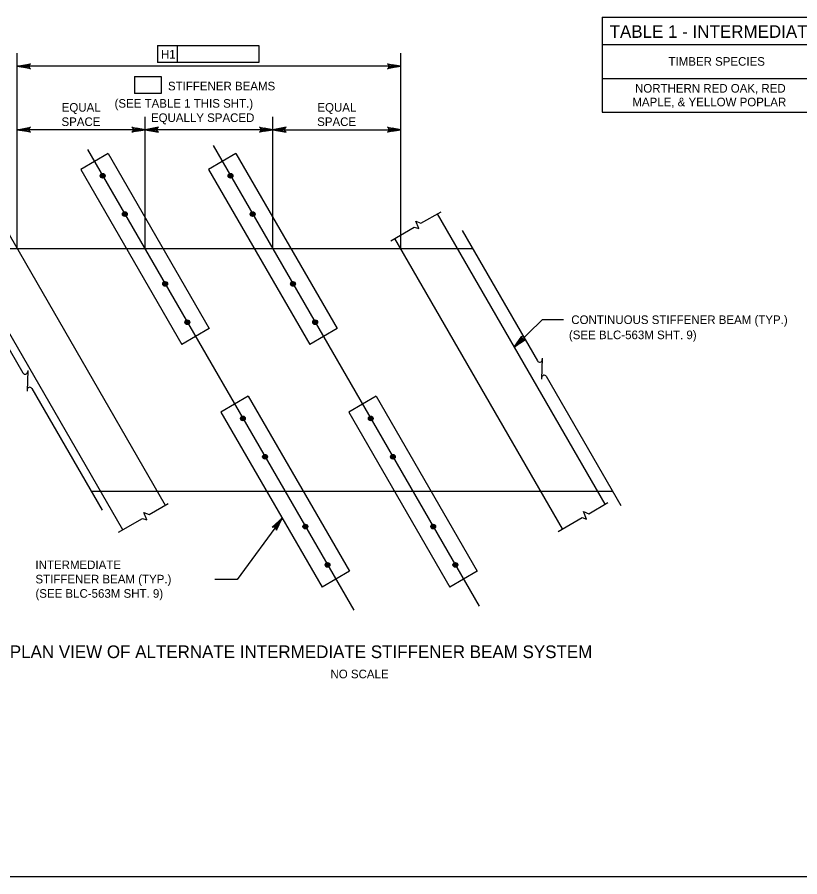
# Model space of a CAD drawing. Extents: x 638268 to 640277, y 295465 to 298435.
# Drawn here: x 639628.9 to 639902.1, y 296668.5 to 296968.5 of the extents above; entities that cross this region are included whole.
import ezdxf

# ---------------------------------------------------------------- set-up
doc = ezdxf.new("R2010")
doc.units = 0
for name, color, linetype in [('2', 7, 'Continuous'), ('3', 7, 'Continuous'), ('4', 7, 'Continuous'), ('8', 7, 'Continuous')]:
    doc.layers.add(name, color=color, linetype=linetype)

msp = doc.modelspace()

# ---------------------------------------------------------------- linework, layer by layer
at = {"layer": '2'}
for p, q in [((639787.93, 296887.61), (639605.87, 296887.61)), ((639836.89, 296802.91), (639654.83, 296802.91)), ((640102.46, 296668.46), (639316.46, 296668.46))]:
    msp.add_line(p, q, dxfattribs=at)
at = {"layer": '3'}
for p, q in [((639660.62, 296920.9), (639651.08, 296915.38)), ((639660.62, 296920.9), (639695.94, 296859.8)), ((639705.26, 296920.9), (639695.71, 296915.38)), ((639705.26, 296920.9), (639740.57, 296859.8)), ((639651.08, 296915.38), (639686.4, 296854.29)), ((639695.71, 296915.38), (639731.03, 296854.29)), ((639769.85, 296896.57), (639776.87, 296900.62)), ((639622.02, 296899.51), (639680.61, 296798.15)), ((639769.07, 296894.71), (639768.05, 296897.31)), ((639768.05, 296897.31), (639769.85, 296896.57)), ((639775.51, 296899.84), (639834.1, 296798.48)), ((639759.35, 296890.5), (639767.51, 296895.22)), ((639767.51, 296895.22), (639769.07, 296894.71)), ((639784.22, 296894.04), (639810.51, 296848.55)), ((639603.62, 296891.5), (639630.89, 296844.33)), ((639819.28, 296789.91), (639760.69, 296891.27)), ((639665.78, 296789.58), (639607.2, 296890.94)), ((639812.2, 296862.83), (639802.41, 296853.32)), ((639695.94, 296859.8), (639686.4, 296854.29)), ((639740.57, 296859.8), (639731.03, 296854.29)), ((639812.22, 296849.46), (639811.95, 296842.19)), ((639632.6, 296845.24), (639632.33, 296837.97)), ((639813.62, 296843.17), (639839.68, 296798.08)), ((639634, 296838.95), (639658.59, 296796.39)), ((639709.58, 296836.2), (639700.04, 296830.68)), ((639709.58, 296836.2), (639744.9, 296775.1)), ((639754.22, 296836.2), (639744.67, 296830.68)), ((639754.22, 296836.2), (639789.54, 296775.1)), ((639700.04, 296830.68), (639735.36, 296769.58)), ((639744.67, 296830.68), (639779.99, 296769.58)), ((639674.95, 296794.88), (639681.64, 296798.75)), ((639828.44, 296795.21), (639835.13, 296799.08)), ((639674.16, 296793.02), (639673.15, 296795.62)), ((639673.15, 296795.62), (639674.95, 296794.88)), ((639827.66, 296793.35), (639826.64, 296795.95)), ((639826.64, 296795.95), (639828.44, 296795.21)), ((639664.29, 296788.72), (639672.61, 296793.53)), ((639672.61, 296793.53), (639674.16, 296793.02)), ((639817.78, 296789.05), (639826.1, 296793.86)), ((639826.1, 296793.86), (639827.66, 296793.35)), ((639744.9, 296775.1), (639735.36, 296769.58)), ((639789.54, 296775.1), (639779.99, 296769.58))]:
    msp.add_line(p, q, dxfattribs=at)
msp.add_lwpolyline([(639802.4, 296853.32), (639805.14, 296857.19), (639805.06, 296856.77), (639805.14, 296856.41), (639805.32, 296856.15), (639805.58, 296855.96), (639805.93, 296855.87), (639806.36, 296855.94), (639802.4, 296853.32), (639805.93, 296855.87), (639805.58, 296855.96), (639802.4, 296853.32), (639805.32, 296856.15), (639805.14, 296856.41), (639802.4, 296853.32), (639805.06, 296856.77)], dxfattribs=at)
for centre, radius in [((639658.73, 296913.16), 0.833), ((639658.73, 296913.16), 0.738), ((639658.73, 296913.16), 0.625), ((639658.73, 296913.16), 0.417), ((639658.73, 296913.16), 0.208), ((639703.37, 296913.16), 0.833), ((639703.37, 296913.16), 0.738), ((639703.37, 296913.16), 0.625), ((639703.37, 296913.16), 0.417), ((639703.37, 296913.16), 0.208), ((639666.47, 296899.78), 0.833), ((639666.47, 296899.78), 0.738), ((639666.47, 296899.78), 0.625), ((639666.47, 296899.78), 0.417), ((639711.1, 296899.78), 0.833), ((639711.1, 296899.78), 0.738), ((639711.1, 296899.78), 0.625), ((639711.1, 296899.78), 0.417), ((639666.47, 296899.78), 0.208), ((639711.1, 296899.78), 0.208), ((639680.55, 296875.41), 0.833), ((639680.55, 296875.41), 0.738), ((639680.55, 296875.41), 0.625), ((639725.19, 296875.41), 0.833), ((639725.19, 296875.41), 0.738), ((639725.19, 296875.41), 0.625), ((639680.55, 296875.41), 0.417), ((639680.55, 296875.41), 0.208), ((639725.19, 296875.41), 0.417), ((639725.19, 296875.41), 0.208), ((639688.29, 296862.03), 0.833), ((639688.29, 296862.03), 0.738), ((639688.29, 296862.03), 0.625), ((639688.29, 296862.03), 0.417), ((639688.29, 296862.03), 0.208), ((639732.92, 296862.03), 0.833), ((639732.92, 296862.03), 0.738), ((639732.92, 296862.03), 0.625), ((639732.92, 296862.03), 0.417), ((639732.92, 296862.03), 0.208), ((639707.69, 296828.46), 0.833), ((639707.69, 296828.46), 0.738), ((639707.69, 296828.46), 0.625), ((639707.69, 296828.46), 0.417), ((639707.69, 296828.46), 0.208), ((639752.33, 296828.46), 0.833), ((639752.33, 296828.46), 0.738), ((639752.33, 296828.46), 0.625), ((639752.33, 296828.46), 0.417), ((639752.33, 296828.46), 0.208), ((639715.43, 296815.08), 0.833), ((639715.43, 296815.08), 0.738), ((639715.43, 296815.08), 0.625), ((639715.43, 296815.08), 0.417), ((639715.43, 296815.08), 0.208), ((639760.06, 296815.08), 0.833), ((639760.06, 296815.08), 0.738), ((639760.06, 296815.08), 0.625), ((639760.06, 296815.08), 0.417), ((639760.06, 296815.08), 0.208), ((639729.51, 296790.71), 0.833), ((639729.51, 296790.71), 0.738), ((639729.51, 296790.71), 0.625), ((639729.51, 296790.71), 0.417), ((639729.51, 296790.71), 0.208), ((639774.15, 296790.71), 0.833), ((639774.15, 296790.71), 0.738), ((639774.15, 296790.71), 0.625), ((639774.15, 296790.71), 0.417), ((639774.15, 296790.71), 0.208), ((639737.25, 296777.33), 0.833), ((639737.25, 296777.33), 0.738), ((639737.25, 296777.33), 0.625), ((639737.25, 296777.33), 0.417), ((639737.25, 296777.33), 0.208), ((639781.88, 296777.33), 0.833), ((639781.88, 296777.33), 0.738), ((639781.88, 296777.33), 0.625), ((639781.88, 296777.33), 0.417), ((639781.88, 296777.33), 0.208)]:
    msp.add_circle(centre, radius, dxfattribs=at)
for centre, start, end in [((639811.3, 296849.01), 210.0292, 0.0292), ((639631.67, 296844.79), 210.0292, 0.0292), ((639812.88, 296842.64), 35.3578, 177.8964), ((639633.26, 296838.42), 35.3578, 177.8964)]:
    msp.add_arc(centre, 0.909, start, end, dxfattribs=at)
at = {"layer": '4'}
for p, q in [((639677.91, 296958.64), (639677.91, 296952.73)), ((639677.91, 296958.64), (639713.21, 296958.64)), ((639684.8, 296958.64), (639684.8, 296952.73)), ((639713.21, 296958.64), (639713.21, 296952.73)), ((639628.9, 296887.61), (639628.9, 296955.91)), ((639762.81, 296887.61), (639762.81, 296955.91)), ((639762.81, 296951.41), (639628.9, 296951.41)), ((639713.21, 296952.73), (639677.91, 296952.73)), ((639669.83, 296947.8), (639679.11, 296947.8)), ((639669.83, 296947.8), (639669.83, 296941.9)), ((639679.11, 296947.8), (639679.11, 296941.9)), ((639679.11, 296941.9), (639669.83, 296941.9)), ((639628.9, 296887.61), (639628.9, 296933.76)), ((639673.54, 296887.61), (639673.54, 296933.76)), ((639718.17, 296887.61), (639718.17, 296933.76)), ((639762.81, 296887.61), (639762.81, 296933.76)), ((639670.54, 296929.26), (639628.9, 296929.26)), ((639715.17, 296929.26), (639676.54, 296929.26)), ((639721.17, 296929.26), (639762.81, 296929.26)), ((639653.49, 296922.3), (639746.39, 296761.57)), ((639697.31, 296923.7), (639790.21, 296762.97)), ((639819.68, 296862.83), (639812.2, 296862.83)), ((639705.75, 296772.23), (639697.91, 296772.23))]:
    msp.add_line(p, q, dxfattribs=at)
for points in [[(639628.9, 296951.41), (639633.56, 296952.28), (639633.2, 296952.03), (639633.02, 296951.72), (639632.96, 296951.41), (639633.02, 296951.1), (639633.2, 296950.78), (639633.56, 296950.54), (639628.9, 296951.41), (639633.2, 296950.78), (639633.02, 296951.1), (639628.9, 296951.41), (639632.96, 296951.41), (639633.02, 296951.72), (639628.9, 296951.41), (639633.2, 296952.03)], [(639762.81, 296951.41), (639758.15, 296950.54), (639758.5, 296950.78), (639758.69, 296951.1), (639758.74, 296951.41), (639758.69, 296951.72), (639758.5, 296952.03), (639758.15, 296952.28), (639762.81, 296951.41), (639758.5, 296952.03), (639758.69, 296951.72), (639762.81, 296951.41), (639758.74, 296951.41), (639758.69, 296951.1), (639762.81, 296951.41), (639758.5, 296950.78)], [(639628.9, 296929.26), (639633.56, 296930.13), (639633.2, 296929.89), (639633.02, 296929.57), (639632.96, 296929.26), (639633.02, 296928.95), (639633.2, 296928.64), (639633.56, 296928.39), (639628.9, 296929.26), (639633.2, 296928.64), (639633.02, 296928.95), (639628.9, 296929.26), (639632.96, 296929.26), (639633.02, 296929.57), (639628.9, 296929.26), (639633.2, 296929.89)], [(639673.54, 296929.26), (639668.87, 296928.39), (639669.23, 296928.64), (639669.42, 296928.95), (639669.47, 296929.26), (639669.42, 296929.57), (639669.23, 296929.89), (639668.87, 296930.13), (639673.54, 296929.26), (639669.23, 296929.89), (639669.42, 296929.57), (639673.54, 296929.26), (639669.47, 296929.26), (639669.42, 296928.95), (639673.54, 296929.26), (639669.23, 296928.64)], [(639673.54, 296929.26), (639678.2, 296928.39), (639677.84, 296928.64), (639677.65, 296928.95), (639677.6, 296929.26), (639677.65, 296929.57), (639677.84, 296929.89), (639678.2, 296930.13), (639673.54, 296929.26), (639677.84, 296929.89), (639677.65, 296929.57), (639673.54, 296929.26), (639677.6, 296929.26), (639677.65, 296928.95), (639673.54, 296929.26), (639677.84, 296928.64)], [(639718.17, 296929.26), (639713.51, 296928.39), (639713.87, 296928.64), (639714.05, 296928.95), (639714.11, 296929.26), (639714.05, 296929.57), (639713.87, 296929.89), (639713.51, 296930.13), (639718.17, 296929.26), (639713.87, 296929.89), (639714.05, 296929.57), (639718.17, 296929.26), (639714.11, 296929.26), (639714.05, 296928.95), (639718.17, 296929.26), (639713.87, 296928.64)], [(639718.17, 296929.26), (639722.83, 296928.39), (639722.47, 296928.64), (639722.29, 296928.95), (639722.23, 296929.26), (639722.29, 296929.57), (639722.47, 296929.89), (639722.83, 296930.13), (639718.17, 296929.26), (639722.47, 296929.89), (639722.29, 296929.57), (639718.17, 296929.26), (639722.23, 296929.26), (639722.29, 296928.95), (639718.17, 296929.26), (639722.47, 296928.64)], [(639762.81, 296929.26), (639758.15, 296928.39), (639758.5, 296928.64), (639758.69, 296928.95), (639758.74, 296929.26), (639758.69, 296929.57), (639758.5, 296929.89), (639758.15, 296930.13), (639762.81, 296929.26), (639758.5, 296929.89), (639758.69, 296929.57), (639762.81, 296929.26), (639758.74, 296929.26), (639758.69, 296928.95), (639762.81, 296929.26), (639758.5, 296928.64)], [(639721.42, 296793.69), (639705.65, 296772.19)], [(639721.42, 296793.69), (639717.96, 296790.45), (639718.37, 296790.59), (639718.74, 296790.56), (639719.02, 296790.41), (639719.24, 296790.18), (639719.38, 296789.85), (639719.37, 296789.41), (639721.42, 296793.69), (639719.38, 296789.85), (639719.24, 296790.18), (639721.42, 296793.69), (639719.02, 296790.41), (639718.74, 296790.56), (639721.42, 296793.69), (639718.37, 296790.59)]]:
    msp.add_lwpolyline(points, dxfattribs=at)
for points in [[(639631.9, 296951.91), (639631.9, 296950.91), (639628.9, 296951.41)], [(639759.81, 296951.91), (639759.81, 296950.91), (639762.81, 296951.41)], [(639631.9, 296929.76), (639631.9, 296928.76), (639628.9, 296929.26)], [(639670.54, 296929.76), (639670.54, 296928.76), (639673.54, 296929.26)], [(639676.54, 296929.76), (639676.54, 296928.76), (639673.54, 296929.26)], [(639715.17, 296929.76), (639715.17, 296928.76), (639718.17, 296929.26)], [(639721.17, 296929.76), (639721.17, 296928.76), (639718.17, 296929.26)], [(639759.81, 296929.76), (639759.81, 296928.76), (639762.81, 296929.26)], [(639721.42, 296793.69), (639719.85, 296791.12), (639719.45, 296791.42)]]:
    msp.add_lwpolyline(points, close=True, dxfattribs=at)
at = {"layer": '8'}
for p, q in [((639833.15, 296968.52), (640055.35, 296968.52)), ((639833.15, 296968.52), (639833.15, 296935.36)), ((639833.15, 296958.99), (640055.35, 296958.99)), ((639833.15, 296947.17), (640055.35, 296947.17)), ((639833.15, 296935.36), (640055.35, 296935.36))]:
    msp.add_line(p, q, dxfattribs=at)

# ---------------------------------------------------------------- texts
at = {"layer": '4'}
for s, height, p in [('TABLE 1 - INTERMEDIATE STIFFENER BEAM DESIGN DATA', 4.4292, (639835.73, 296961.31)), ('H1', 3, (639679.09, 296954.1)), ('TIMBER SPECIES', 3, (639856.29, 296951.58)), ('STIFFENER BEAMS', 3, (639681.53, 296942.98)), ('NORTHERN RED OAK, RED', 3, (639844.6, 296942.2)), ('(SEE TABLE 1 THIS SHT.)', 3, (639662.89, 296936.94)), ('MAPLE, & YELLOW POPLAR', 3, (639843.67, 296937.42)), ('EQUAL', 3, (639644.43, 296935.54)), ('EQUAL', 3, (639733.7, 296935.54)), ('SPACE', 3, (639644.36, 296930.54)), ('EQUALLY SPACED', 3, (639675.59, 296931.94)), ('SPACE', 3, (639733.63, 296930.54)), ('CONTINUOUS STIFFENER BEAM (TYP.)', 3, (639822.35, 296861.42)), ('(SEE BLC-563M SHT. 9)', 3, (639821.53, 296856.13)), ('INTERMEDIATE', 3, (639635.26, 296775.87)), ('STIFFENER BEAM (TYP.)', 3, (639635.26, 296770.87)), ('(SEE BLC-563M SHT. 9)', 3, (639635.26, 296765.87)), ('PLAN VIEW OF ALTERNATE INTERMEDIATE STIFFENER BEAM SYSTEM', 4.4292, (639626.31, 296744.8)), ('NO SCALE', 3, (639738.27, 296737.75))]:
    msp.add_text(s, height=height, dxfattribs=at).set_placement(p)

doc.saveas('drawing.dxf')
